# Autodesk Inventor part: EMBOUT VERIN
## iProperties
Created: 2004-11
Part Number: EMBOUT VERIN
Document SubType Name: Modeling
Designer: Bruno
Manufacturer: Standard
Standards Organization: Custom
Author: Bruno
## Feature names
1. Base1
2. Extrusion1
